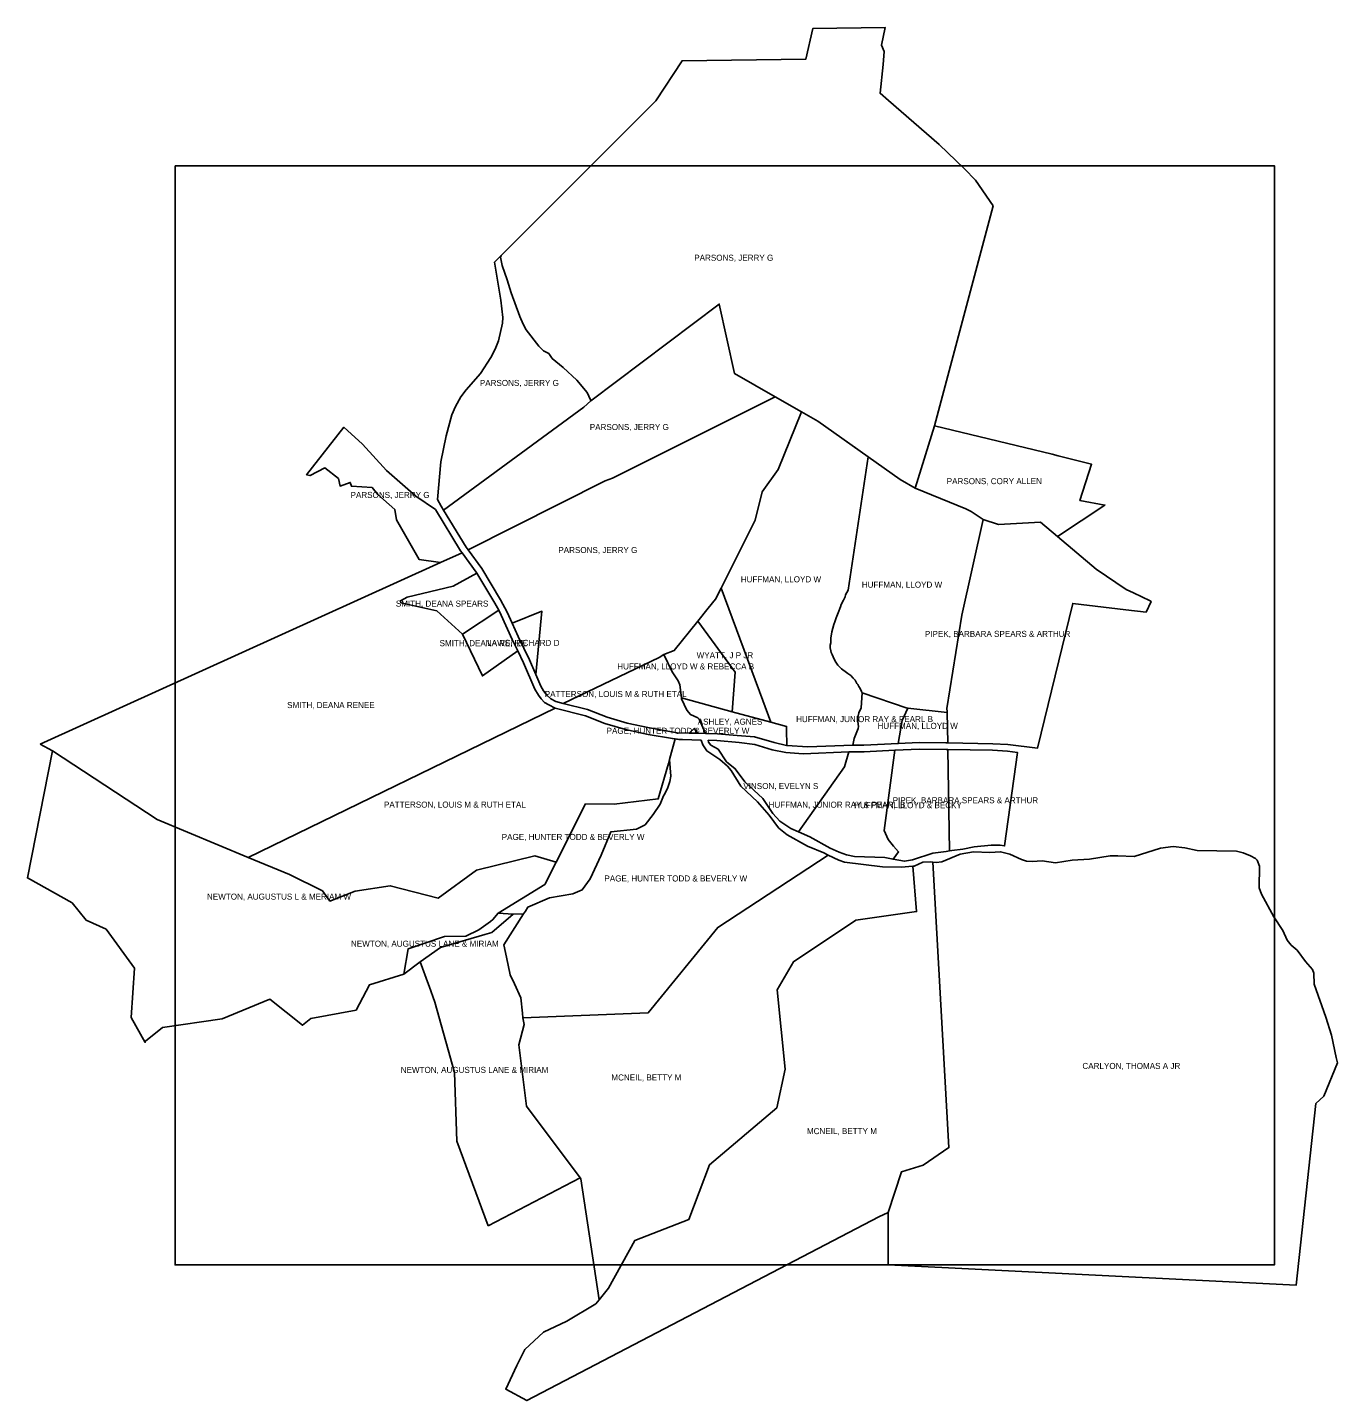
# Model space of a CAD drawing. Extents: x 1301152 to 1307111, y 901737 to 907984.
import ezdxf

# ---------------------------------------------------------------- set-up
doc = ezdxf.new("R2010")
doc.units = 0
doc.layers.add('Default', color=7, linetype='Continuous')
doc.layers.add('Old_Level_3', color=7, linetype='Continuous')

msp = doc.modelspace()

# ---------------------------------------------------------------- linework, layer by layer
at = {"layer": 'Default'}
msp.add_lwpolyline([(1301823.6, 907354.4), (1306823.6, 907354.4), (1306823.6, 902354.4), (1301823.6, 902354.4)], close=True, dxfattribs=at)
at = {"layer": 'Old_Level_3'}
for points in [[(1303306.6, 906946), (1303986.5, 907625.9), (1304010, 907649.4), (1304130, 907831.9), (1304692.9, 907839.9), (1304724.1, 907978.5), (1305052.9, 907983.7), (1305037.2, 907903.9), (1305048.9, 907873.9), (1305044.9, 907815.4), (1305030.4, 907684.5), (1305067.8, 907651.9), (1305299.5, 907450.9), (1305414.4, 907341.2), (1305463.6, 907288.8), (1305545.2, 907172.4), (1305277.8, 906171.5), (1305189.1, 905888.5), (1305122.1, 905926.9), (1304747.2, 906192.9), (1304673.5, 906234.8), (1304552.6, 906303.9), (1304368.1, 906409.4), (1304298.5, 906725), (1303714.2, 906285.6), (1303713.8, 906289.8), (1303698.4, 906322.8), (1303650.6, 906378.6), (1303589.4, 906436.9), (1303539.2, 906477.1), (1303522.9, 906500.6), (1303499.9, 906513.2), (1303478.1, 906533.7), (1303421.1, 906607.9), (1303406.6, 906633.8), (1303392, 906669.4), (1303351.8, 906776.6), (1303334.5, 906836.2), (1303312.1, 906901), (1303304.4, 906938.4)], [(1303017.9, 905836.9), (1303032.9, 906007.8), (1303056.2, 906125.8), (1303082.6, 906221.8), (1303099.4, 906259.8), (1303123.8, 906303.7), (1303148.1, 906335.7), (1303213.5, 906409.2), (1303259.4, 906481.6), (1303279.8, 906520.2), (1303294.5, 906558.5), (1303313.2, 906638.5), (1303314.1, 906664.6), (1303305.1, 906743.8), (1303275.9, 906915.4), (1303283, 906922.4), (1303306.6, 906946), (1303304.4, 906938.4), (1303312.1, 906901), (1303334.5, 906836.2), (1303351.8, 906776.6), (1303392, 906669.4), (1303406.6, 906633.8), (1303421.1, 906607.9), (1303478.1, 906533.7), (1303499.9, 906513.2), (1303522.9, 906500.6), (1303539.2, 906477.1), (1303589.4, 906436.9), (1303650.6, 906378.6), (1303698.4, 906322.8), (1303713.8, 906289.8), (1303714.2, 906285.6), (1303682.4, 906256.9), (1303045.1, 905787.3), (1303034, 905805.7)], [(1303045.1, 905787.3), (1303682.4, 906256.9), (1303714.2, 906285.6), (1304298.5, 906725), (1304368.1, 906409.4), (1304552.6, 906303.9), (1303813.9, 905933.7), (1303780.1, 905920.7), (1303156.4, 905607), (1303147.1, 905619.7)], [(1303356.2, 905273.8), (1303333.9, 905323.7), (1303304.5, 905379.5), (1303218.4, 905522.6), (1303156.4, 905607), (1303780.1, 905920.7), (1303813.9, 905933.7), (1304552.6, 906303.9), (1304673.5, 906234.8), (1304566.5, 905972.6), (1304494.1, 905870.6), (1304461.4, 905742.6), (1304306.8, 905432.4), (1304282.1, 905383.1), (1304248.6, 905341.4), (1304201.5, 905282.9), (1304093.8, 905149.1), (1304047.4, 905131.1), (1304025, 905117.3), (1303589, 904908.8), (1303555.9, 904917.2), (1303532.2, 904929.8), (1303514.8, 904946), (1303499.8, 904965.6), (1303487.2, 904986.8), (1303464.5, 905040.4), (1303492.1, 905327.9)], [(1304497, 904921.2), (1304306.8, 905432.4), (1304461.4, 905742.6), (1304494.1, 905870.6), (1304566.5, 905972.6), (1304673.5, 906234.8), (1304747.2, 906192.9), (1304975.5, 906030.9), (1304884.4, 905423.8), (1304873.5, 905403), (1304870.8, 905393), (1304864.2, 905379), (1304853.5, 905358.2), (1304849.9, 905348.2), (1304839.5, 905320.6), (1304829.9, 905297.8), (1304824.2, 905280.1), (1304819.5, 905266.9), (1304810.2, 905234.5), (1304805.9, 905204.9), (1304805.5, 905184.9), (1304803.9, 905174.1), (1304803.9, 905161.6), (1304805.5, 905148), (1304807.9, 905140.8), (1304811.9, 905131.6), (1304816.2, 905121.2), (1304826.2, 905101.6), (1304837.5, 905083.2), (1304843.1, 905078.8), (1304849.1, 905072), (1304855.1, 905066.4), (1304861.1, 905061.6), (1304871.1, 905053.6), (1304883.9, 905045.1), (1304892.4, 905038.4), (1304896.8, 905035.1), (1304907.9, 905023.9), (1304911.9, 905019.1), (1304916.4, 905014.3), (1304920.8, 905005.5), (1304924.8, 904999.5), (1304928.8, 904995.1), (1304934, 904985.9), (1304936.1, 904981.8), (1304938.9, 904977.2), (1304946.2, 904962.1), (1304949.4, 904956.1), (1304944.2, 904887.8), (1304933.6, 904865.3), (1304927.5, 904838.7), (1304932.1, 904803.9), (1304930.6, 904795.1), (1304912.1, 904748.7), (1304907, 904718.4), (1304700.9, 904711.8), (1304606, 904717.5), (1304605, 904790.2), (1304604.9, 904803.7), (1304533.5, 904823.1)], [(1302830.6, 905744.2), (1302823.4, 905790.2), (1302745.9, 905858.6), (1302719.9, 905891.4), (1302625.9, 905896.6), (1302620.6, 905913.8), (1302574.2, 905897.4), (1302567, 905931.1), (1302504.6, 905980.2), (1302437.4, 905945.1), (1302421.5, 905949.1), (1302592, 906165.3), (1302675.4, 906087.7), (1302785, 905967.5), (1302919.2, 905851.8), (1303008, 905790.8), (1303122.1, 905602.9), (1303128.9, 905593.8), (1303030.2, 905549), (1302933.4, 905563.4)], [(1305189.1, 905888.5), (1305277.8, 906171.5), (1305812.9, 906042.5), (1305840, 906035.6), (1305991.8, 905996.8), (1305938.8, 905831.1), (1306052.8, 905810.8), (1305836.9, 905668.1), (1305760.2, 905732.5), (1305569.1, 905722.5), (1305498.5, 905745.6), (1305444.5, 905781.7), (1305420.4, 905794.1)], [(1304884.4, 905423.8), (1304975.5, 906030.9), (1305122.1, 905926.9), (1305189.1, 905888.5), (1305420.4, 905794.1), (1305444.5, 905781.7), (1305498.5, 905745.6), (1305401.4, 905310.2), (1305334.1, 904886.1), (1305335.5, 904872.6), (1305335.6, 904866.8), (1305157, 904887.1), (1305152.9, 904887.5), (1304949.4, 904956.1), (1304946.2, 904962.1), (1304938.9, 904977.2), (1304936.1, 904981.8), (1304934, 904985.9), (1304928.8, 904995.1), (1304924.8, 904999.5), (1304920.8, 905005.5), (1304916.4, 905014.3), (1304911.9, 905019.1), (1304907.9, 905023.9), (1304896.8, 905035.1), (1304892.4, 905038.4), (1304883.9, 905045.1), (1304871.1, 905053.6), (1304861.1, 905061.6), (1304855.1, 905066.4), (1304849.1, 905072), (1304843.1, 905078.8), (1304837.5, 905083.2), (1304826.2, 905101.6), (1304816.2, 905121.2), (1304811.9, 905131.6), (1304807.9, 905140.8), (1304805.5, 905148), (1304803.9, 905161.6), (1304803.9, 905174.1), (1304805.5, 905184.9), (1304805.9, 905204.9), (1304810.2, 905234.5), (1304819.5, 905266.9), (1304824.2, 905280.1), (1304829.9, 905297.8), (1304839.5, 905320.6), (1304849.9, 905348.2), (1304853.5, 905358.2), (1304864.2, 905379), (1304870.8, 905393), (1304873.5, 905403)], [(1305334.1, 904886.1), (1305401.4, 905310.2), (1305498.5, 905745.6), (1305569.1, 905722.5), (1305760.2, 905732.5), (1305836.9, 905668.1), (1306013.4, 905519.7), (1306150.1, 905427.6), (1306183.2, 905411.4), (1306258, 905374.9), (1306262.9, 905372.5), (1306240.1, 905324.1), (1306148.1, 905334.5), (1305906.4, 905363.3), (1305746, 904704.4), (1305611.8, 904721.6), (1305543.2, 904725.4), (1305337.8, 904728.7), (1305335.6, 904866.8), (1305335.5, 904872.6)], [(1301210, 904722.6), (1303030.2, 905549), (1303128.9, 905593.8), (1303193.4, 905505.9), (1303196.1, 905501.4), (1303087.8, 905442.7), (1302878.6, 905392.2), (1302848.6, 905375.9), (1302850.2, 905366.5), (1303014.6, 905329.1), (1303131.6, 905224.2), (1303221.4, 905033.5), (1303382.6, 905147.3), (1303409.1, 905093.9), (1303460.5, 904973.3), (1303476.5, 904946.1), (1303488.5, 904929.6), (1303504.4, 904912.9), (1303524.2, 904902), (1303552.5, 904887.1), (1302156.6, 904208.2), (1301742.2, 904380.3), (1301265.9, 904693.1)], [(1303014.6, 905329.1), (1302850.2, 905366.5), (1302848.6, 905375.9), (1302878.6, 905392.2), (1303087.8, 905442.7), (1303196.1, 905501.4), (1303278.2, 905364.7), (1303295.5, 905332.1), (1303131.6, 905224.2)], [(1304371.8, 905050.5), (1304201.5, 905282.9), (1304248.6, 905341.4), (1304282.1, 905383.1), (1304306.8, 905432.4), (1304497, 904921.2), (1304533.5, 904823.1), (1304357.5, 904870.9)], [(1303221.4, 905033.5), (1303131.6, 905224.2), (1303295.5, 905332.1), (1303306.9, 905310.6), (1303356.4, 905200), (1303382.6, 905147.3)], [(1303464.5, 905040.4), (1303436.4, 905106.4), (1303383.6, 905212.7), (1303356.2, 905273.8), (1303492.1, 905327.9)], [(1304126.6, 904933.7), (1304120, 904993.6), (1304111.8, 905011.1), (1304084.1, 905052.2), (1304047.4, 905131.1), (1304093.8, 905149.1), (1304201.5, 905282.9), (1304371.8, 905050.5), (1304357.5, 904870.9)], [(1303589, 904908.8), (1304025, 905117.3), (1304047.4, 905131.1), (1304084.1, 905052.2), (1304111.8, 905011.1), (1304120, 904993.6), (1304126.6, 904933.7), (1304127.1, 904929.1), (1304151.9, 904877.4), (1304167.8, 904857.9), (1304201.8, 904843.1), (1304206.7, 904836.8), (1304236.1, 904771.5), (1304197.1, 904772.7), (1304188, 904792.1), (1304185.4, 904795.3), (1304162.4, 904773.7), (1304108, 904775.4), (1303980.9, 904797.3), (1303879.2, 904819.4), (1303788.4, 904846.1), (1303699.9, 904880.4)], [(1304236.1, 904771.5), (1304206.7, 904836.8), (1304201.8, 904843.1), (1304167.8, 904857.9), (1304151.9, 904877.4), (1304127.1, 904929.1), (1304126.6, 904933.7), (1304357.5, 904870.9), (1304533.5, 904823.1), (1304604.9, 904803.7), (1304605, 904790.2), (1304606, 904717.5), (1304604.5, 904717.6), (1304548.1, 904731.5), (1304459.6, 904756.8), (1304379.8, 904763.2), (1304290.1, 904769.9)], [(1304907, 904718.4), (1304912.1, 904748.7), (1304930.6, 904795.1), (1304932.1, 904803.9), (1304927.5, 904838.7), (1304933.6, 904865.3), (1304944.2, 904887.8), (1304949.4, 904956.1), (1305152.9, 904887.5), (1305157, 904887.1), (1305130.5, 904830.7), (1305112.8, 904726.2), (1304956.8, 904718.6), (1304923.4, 904718.5)], [(1302156.6, 904208.2), (1303552.5, 904887.1), (1303690.6, 904851.8), (1303778.6, 904817.8), (1303871.9, 904789.9), (1303975.1, 904767.8), (1304085.9, 904748.8), (1304098.1, 904746.8), (1304072.2, 904652.8), (1304067.4, 904635.6), (1304021.5, 904474.4), (1303821.4, 904449.9), (1303691, 904451.1), (1303556.6, 904187.1), (1303459.4, 904215.1), (1303195, 904150.8), (1303020.2, 904022.8), (1302802.6, 904078.8), (1302643, 904055.1), (1302528.2, 904009.6), (1302493.9, 904056.4), (1302344.2, 904130.4)], [(1305112.8, 904726.2), (1305130.5, 904830.7), (1305157, 904887.1), (1305335.6, 904866.8), (1305337.8, 904728.7), (1305329.2, 904728.9), (1305208.4, 904730.9)], [(1304162.4, 904773.7), (1304185.4, 904795.3), (1304188, 904792.1), (1304197.1, 904772.7)], [(1303428.5, 903981.9), (1303526.6, 904024.2), (1303633, 904041.9), (1303675.4, 904059.9), (1303712.2, 904109.9), (1303761, 904217.9), (1303806.2, 904324.8), (1303921.9, 904337.1), (1303934, 904343.1), (1303961.5, 904356.8), (1303998.2, 904402.7), (1304030.2, 904450.8), (1304042.2, 904481.1), (1304045, 904487.9), (1304047.6, 904493.1), (1304062.6, 904521.9), (1304074.2, 904552.8), (1304078.2, 904577.2), (1304072.2, 904652.8), (1304098.1, 904746.8), (1304105, 904745.6), (1304108.8, 904745.4), (1304115.1, 904745.2), (1304131.6, 904744.8), (1304215.9, 904742.1), (1304224.5, 904720.9), (1304242.9, 904692.7), (1304301.1, 904654.2), (1304335.5, 904623), (1304352.5, 904603.5), (1304396.5, 904531.9), (1304472.5, 904460.5), (1304525, 904400.6), (1304568.4, 904342.9), (1304570, 904340.8), (1304607, 904311.2), (1304700.1, 904258.7), (1304774.9, 904228.3), (1304794.1, 904218.9), (1304292.2, 903889.4), (1303975.5, 903501.4), (1303406, 903478), (1303403.8, 903500), (1303396.4, 903569.6), (1303366.9, 903632.8), (1303347.6, 903673.9), (1303330.9, 903754.1), (1303318.9, 903811.1), (1303408.1, 903951.1), (1303416.8, 903964.1)], [(1304659.8, 904324.1), (1304623.8, 904340), (1304573.7, 904372.7), (1304542.9, 904407.7), (1304496.6, 904476.4), (1304415.6, 904551.6), (1304371.1, 904611.4), (1304331.4, 904643.1), (1304293.5, 904701.1), (1304260, 904719), (1304249.9, 904731.9), (1304248.5, 904741.1), (1304288.4, 904739.9), (1304389.4, 904731.4), (1304459.8, 904721.2), (1304538.9, 904698.2), (1304601.8, 904684.7), (1304680.9, 904679), (1304888.2, 904688.4), (1304868.4, 904620.4)], [(1301509.9, 903881.2), (1301418.8, 903923.2), (1301355.5, 904001.9), (1301152.4, 904114.8), (1301265.9, 904693.1), (1301742.2, 904380.3), (1302156.6, 904208.2), (1302344.2, 904130.4), (1302493.9, 904056.4), (1302528.2, 904009.6), (1302643, 904055.1), (1302802.6, 904078.8), (1303020.2, 904022.8), (1303195, 904150.8), (1303459.4, 904215.1), (1303556.6, 904187.1), (1303505.8, 904085.5), (1303293.5, 903954.6), (1303269.2, 903924.9), (1303258.1, 903916.1), (1303205.2, 903878.4), (1303146.5, 903850.4), (1303049.2, 903848.9), (1302884.1, 903792.9), (1302863.9, 903676.6), (1302708, 903628.6), (1302647.2, 903512.7), (1302441.8, 903475.1), (1302403.1, 903444.3), (1302255, 903563.6), (1302038.2, 903474.4), (1301766.2, 903434.4), (1301689.9, 903372), (1301688.2, 903366.3), (1301623.9, 903480), (1301639.1, 903704)], [(1304659.8, 904324.1), (1304868.4, 904620.4), (1304888.2, 904688.4), (1304899.2, 904688.4), (1304957.5, 904688.6), (1305098, 904695.4), (1305048.1, 904331), (1305066.6, 904289.4), (1305091, 904258.6), (1305114.6, 904233.3), (1305089.6, 904200.1), (1305052.5, 904207.1), (1304914.1, 904211.6), (1304877.2, 904219.1), (1304844.4, 904232.3), (1304803.8, 904250.8), (1304710.6, 904301.6)], [(1305089.6, 904200.1), (1305114.6, 904233.3), (1305091, 904258.6), (1305066.6, 904289.4), (1305048.1, 904331), (1305098, 904695.4), (1305208.9, 904700.9), (1305330.4, 904698.9), (1305338.2, 904698.7), (1305345.6, 904237.4), (1305331.1, 904235.4), (1305270.8, 904226.7), (1305177.4, 904197), (1305141.6, 904190.3)], [(1305345.6, 904237.4), (1305338.2, 904698.7), (1305542.2, 904695.4), (1305609, 904691.8), (1305655.1, 904685.8), (1305596.6, 904260.3), (1305576.5, 904263.6), (1305535.6, 904263.4), (1305458.2, 904256.4), (1305407.2, 904246.3), (1305356.9, 904239.1)], [(1303556.6, 904187.1), (1303691, 904451.1), (1303821.4, 904449.9), (1304021.5, 904474.4), (1304067.4, 904635.6), (1304072.2, 904652.8), (1304078.2, 904577.2), (1304074.2, 904552.8), (1304062.6, 904521.9), (1304047.6, 904493.1), (1304045, 904487.9), (1304042.2, 904481.1), (1304030.2, 904450.8), (1303998.2, 904402.7), (1303961.5, 904356.8), (1303934, 904343.1), (1303921.9, 904337.1), (1303806.2, 904324.8), (1303761, 904217.9), (1303712.2, 904109.9), (1303675.4, 904059.9), (1303633, 904041.9), (1303526.6, 904024.2), (1303428.5, 903981.9), (1303416.8, 903964.1), (1303408.1, 903951.1), (1303361.4, 903949.9), (1303293.5, 903954.6), (1303505.8, 904085.5)], [(1305343.6, 902888.4), (1305270, 904187.2), (1305286, 904185.1), (1305311.2, 904188.4), (1305393.8, 904223.1), (1305455.6, 904233.5), (1305528.8, 904231.1), (1305578.2, 904233.9), (1305620.2, 904223.1), (1305674, 904197.9), (1305695.8, 904191.7), (1305722.6, 904189.9), (1305767.5, 904192.7), (1305827.4, 904183.9), (1305904, 904196.3), (1305983.2, 904200.7), (1306076.2, 904214.6), (1306110.9, 904215.9), (1306186, 904211.5), (1306305.6, 904249.6), (1306363, 904257.4), (1306415.8, 904251.9), (1306473.1, 904239.1), (1306650.8, 904237.2), (1306682, 904229.1), (1306715.1, 904215.6), (1306737.1, 904203.9), (1306745.9, 904195.2), (1306755.6, 904168.4), (1306754.6, 904070.3), (1306764.8, 904040.4), (1306820.5, 903937.1), (1306861.8, 903875.4), (1306882.1, 903832.1), (1306900.1, 903809.6), (1306927.6, 903785.6), (1306965.5, 903734.3), (1306997, 903697.8), (1307002.8, 903681.2), (1307005, 903632.2), (1307057.5, 903482), (1307084, 903400), (1307104.4, 903298), (1307110.8, 903273.5), (1307048, 903122), (1307012.4, 903088.4), (1306922, 902261.7), (1305067.2, 902354.4), (1305066.6, 902592.2), (1305127, 902777.4), (1305225.6, 902808)], [(1304254.5, 902809.6), (1304560.1, 903068.4), (1304599.2, 903244.8), (1304562.1, 903606), (1304636.9, 903733.6), (1304920.5, 903921.9), (1305196.5, 903961.6), (1305178.6, 904168.2), (1305185.2, 904168.7), (1305224.9, 904186.1), (1305260.1, 904188.6), (1305270, 904187.2), (1305343.6, 902888.4), (1305225.6, 902808), (1305127, 902777.4), (1305066.6, 902592.2), (1305025.2, 902572.4), (1303423.4, 901737.3), (1303327.8, 901788.5), (1303377.7, 901896.5), (1303415, 901968.9), (1303499.4, 902048.5), (1303606.1, 902098.1), (1303738.1, 902177.7), (1303752, 902195.2), (1303794.5, 902248.9), (1303914.1, 902465.2), (1304159.8, 902560.4)], [(1303386.5, 903355.2), (1303411.2, 903448.7), (1303406, 903478), (1303975.5, 903501.4), (1304292.2, 903889.4), (1304794.1, 904218.9), (1304841.9, 904195.4), (1304869, 904187.1), (1305040.9, 904165.4), (1305126.1, 904164.4), (1305178.6, 904168.2), (1305196.5, 903961.6), (1304920.5, 903921.9), (1304636.9, 903733.6), (1304562.1, 903606), (1304599.2, 903244.8), (1304560.1, 903068.4), (1304254.5, 902809.6), (1304159.8, 902560.4), (1303914.1, 902465.2), (1303794.5, 902248.9), (1303752, 902195.2), (1303669.8, 902746.4), (1303666.5, 902750.8), (1303421.8, 903076.8)], [(1302863.9, 903676.6), (1302884.1, 903792.9), (1303049.2, 903848.9), (1303146.5, 903850.4), (1303205.2, 903878.4), (1303258.1, 903916.1), (1303269.2, 903924.9), (1303293.5, 903954.6), (1303361.4, 903949.9), (1303264.6, 903865.9), (1303232.4, 903856.7), (1303030.5, 903798.9), (1302938.2, 903732.9)], [(1303248.2, 902531.9), (1303105.8, 902917.1), (1303094.5, 903230.1), (1303005.4, 903550.3), (1302979, 903622.9), (1302976.6, 903629.4), (1302938.2, 903732.9), (1303030.5, 903798.9), (1303232.4, 903856.7), (1303264.6, 903865.9), (1303361.4, 903949.9), (1303408.1, 903951.1), (1303318.9, 903811.1), (1303330.9, 903754.1), (1303347.6, 903673.9), (1303366.9, 903632.8), (1303396.4, 903569.6), (1303403.8, 903500), (1303406, 903478), (1303411.2, 903448.7), (1303386.5, 903355.2), (1303421.8, 903076.8), (1303666.5, 902750.8)]]:
    msp.add_lwpolyline(points, close=True, dxfattribs=at)

# ---------------------------------------------------------------- texts
for s, p in [('PARSONS, JERRY G', (1304185.1, 906922.4)), ('PARSONS, JERRY G', (1303209.9, 906352.9)), ('PARSONS, JERRY G', (1303709.9, 906152.3)), ('PARSONS, CORY ALLEN', (1305333.4, 905906.1)), ('PARSONS, JERRY G', (1302621.9, 905843.4)), ('PARSONS, JERRY G', (1303566.8, 905592.6)), ('HUFFMAN, LLOYD W', (1304396.5, 905459.5)), ('HUFFMAN, LLOYD W', (1304947.2, 905435.1)), ('SMITH, DEANA SPEARS', (1302827.9, 905349)), ('PIPEK, BARBARA SPEARS & ARTHUR', (1305234.1, 905211.3)), ('SMITH, DEANA RENEE', (1303026.7, 905169)), ('LAWS, RICHARD D', (1303243.4, 905170.4)), ('WYATT, J P JR', (1304195.9, 905114)), ('HUFFMAN, LLOYD W & REBECCA B', (1303834.7, 905063.2)), ('SMITH, DEANA RENEE', (1302333.3, 904887.3)), ('PATTERSON, LOUIS M & RUTH ETAL', (1303505.1, 904937.5)), ('HUFFMAN, JUNIOR RAY & PEARL B', (1304648.2, 904823.5)), ('PAGE, HUNTER TODD & BEVERLY W', (1303786.4, 904770.3)), ('ASHLEY, AGNES', (1304200.8, 904811.9)), ('HUFFMAN, LLOYD W', (1305018.5, 904792.9)), ('VINSON, EVELYN S', (1304408.3, 904518.9)), ('PIPEK, BARBARA SPEARS & ARTHUR', (1305087.4, 904454.4)), ('PATTERSON, LOUIS M & RUTH ETAL', (1302773.7, 904434.6)), ('HUFFMAN, JUNIOR RAY & PEARL B', (1304523, 904434)), ('HUFFMAN, LLOYD & BECKY', (1304912.2, 904431.9)), ('PAGE, HUNTER TODD & BEVERLY W', (1303309.4, 904287.6)), ('PAGE, HUNTER TODD & BEVERLY W', (1303776.4, 904098.6)), ('NEWTON, AUGUSTUS L & MERIAM W', (1301968.8, 904016)), ('NEWTON, AUGUSTUS LANE & MIRIAM', (1302623.8, 903801.9)), ('NEWTON, AUGUSTUS LANE & MIRIAM', (1302849.9, 903227.8)), ('CARLYON, THOMAS A JR', (1305950.4, 903245.8)), ('MCNEIL, BETTY M', (1303808, 903193.3)), ('MCNEIL, BETTY M', (1304697.4, 902949.2))]:
    msp.add_text(s, height=27.481, dxfattribs=at).set_placement(p)

doc.saveas('drawing.dxf')
